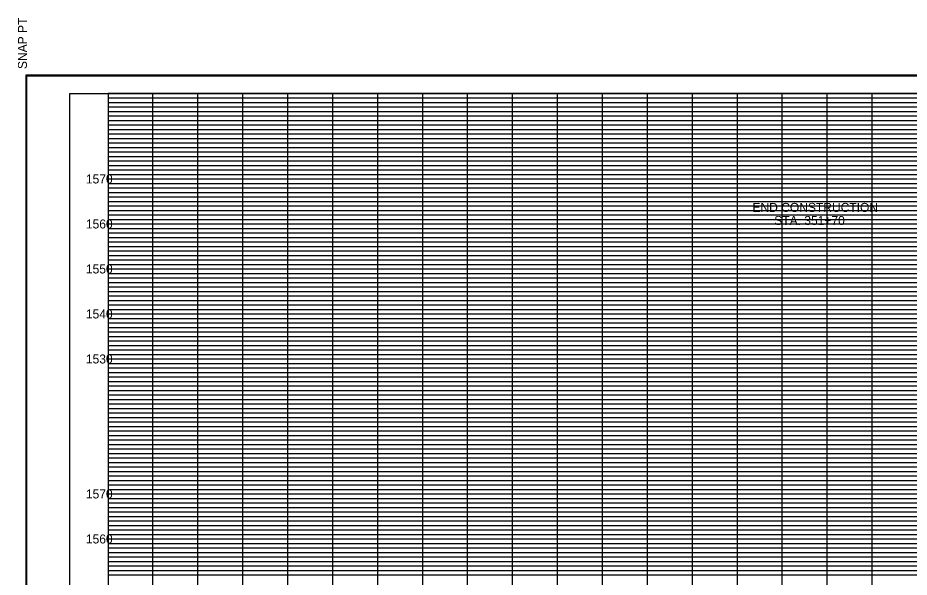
# Model space of a CAD drawing. Extents: x 980 to 1375, y 978 to 1227.
# Drawn here: x 979.9 to 1178.2, y 1102.5 to 1226.8 of the extents above; entities that cross this region are included whole.
import ezdxf

# ---------------------------------------------------------------- set-up
doc = ezdxf.new("R2010")
doc.units = 0
for name, color, linetype in [('DESIGN - SHEET - Corner Text', 7, 'Continuous'), ('DESIGN - SHEET - Light Grid', 7, 'Continuous'), ('DESIGN - SHEET - Linework', 7, 'Continuous'), ('DESIGN - SHEET - Plot Shape', 7, 'Continuous'), ('DESIGN - TYPICAL - Text', 7, 'Continuous')]:
    doc.layers.add(name, color=color, linetype=linetype)

msp = doc.modelspace()

# ---------------------------------------------------------------- linework, layer by layer
at = {"layer": 'DESIGN - SHEET - Light Grid'}
for p, q in [((1000, 1209), (1080, 1209)), ((1000, 1208), (1080, 1208)), ((1080, 1209), (1160, 1209)), ((1080, 1208), (1160, 1208)), ((1160, 1209), (1240, 1209)), ((1160, 1208), (1240, 1208)), ((1000, 1207), (1080, 1207)), ((1000, 1206), (1080, 1206)), ((1080, 1207), (1160, 1207)), ((1080, 1206), (1160, 1206)), ((1160, 1207), (1240, 1207)), ((1160, 1206), (1240, 1206)), ((1000, 1205), (1080, 1205)), ((1000, 1204), (1080, 1204)), ((1080, 1205), (1160, 1205)), ((1080, 1204), (1160, 1204)), ((1160, 1205), (1240, 1205)), ((1160, 1204), (1240, 1204)), ((1000, 1203), (1080, 1203)), ((1000, 1202), (1080, 1202)), ((1080, 1203), (1160, 1203)), ((1080, 1202), (1160, 1202)), ((1160, 1203), (1240, 1203)), ((1160, 1202), (1240, 1202)), ((1000, 1201), (1080, 1201)), ((1080, 1201), (1160, 1201)), ((1160, 1201), (1240, 1201)), ((1000, 1199), (1080, 1199)), ((1000, 1198), (1080, 1198)), ((1080, 1199), (1160, 1199)), ((1080, 1198), (1160, 1198)), ((1160, 1199), (1240, 1199)), ((1160, 1198), (1240, 1198)), ((1000, 1197), (1080, 1197)), ((1000, 1196), (1080, 1196)), ((1080, 1197), (1160, 1197)), ((1080, 1196), (1160, 1196)), ((1160, 1197), (1240, 1197)), ((1160, 1196), (1240, 1196)), ((1000, 1195), (1080, 1195)), ((1000, 1194), (1080, 1194)), ((1080, 1195), (1160, 1195)), ((1080, 1194), (1160, 1194)), ((1160, 1195), (1240, 1195)), ((1160, 1194), (1240, 1194)), ((1000, 1193), (1080, 1193)), ((1000, 1192), (1080, 1192)), ((1080, 1193), (1160, 1193)), ((1080, 1192), (1160, 1192)), ((1160, 1193), (1240, 1193)), ((1160, 1192), (1240, 1192)), ((1000, 1191), (1080, 1191)), ((1080, 1191), (1160, 1191)), ((1160, 1191), (1240, 1191)), ((1000, 1189), (1080, 1189)), ((1000, 1188), (1080, 1188)), ((1080, 1189), (1160, 1189)), ((1080, 1188), (1160, 1188)), ((1160, 1189), (1240, 1189)), ((1160, 1188), (1240, 1188)), ((1000, 1187), (1080, 1187)), ((1000, 1186), (1080, 1186)), ((1080, 1187), (1160, 1187)), ((1080, 1186), (1160, 1186)), ((1160, 1187), (1240, 1187)), ((1160, 1186), (1240, 1186)), ((1000, 1185), (1080, 1185)), ((1000, 1184), (1080, 1184)), ((1080, 1185), (1160, 1185)), ((1080, 1184), (1160, 1184)), ((1160, 1185), (1240, 1185)), ((1160, 1184), (1240, 1184)), ((1000, 1183), (1080, 1183)), ((1000, 1182), (1080, 1182)), ((1080, 1183), (1160, 1183)), ((1080, 1182), (1160, 1182)), ((1160, 1183), (1240, 1183)), ((1160, 1182), (1240, 1182)), ((1000, 1181), (1080, 1181)), ((1080, 1181), (1160, 1181)), ((1160, 1181), (1240, 1181)), ((1000, 1179), (1080, 1179)), ((1000, 1178), (1080, 1178)), ((1080, 1179), (1160, 1179)), ((1080, 1178), (1160, 1178)), ((1160, 1179), (1240, 1179)), ((1160, 1178), (1240, 1178)), ((1000, 1177), (1080, 1177)), ((1000, 1176), (1080, 1176)), ((1080, 1177), (1160, 1177)), ((1080, 1176), (1160, 1176)), ((1160, 1177), (1240, 1177)), ((1160, 1176), (1240, 1176)), ((1000, 1175), (1080, 1175)), ((1000, 1174), (1080, 1174)), ((1080, 1175), (1160, 1175)), ((1080, 1174), (1160, 1174)), ((1160, 1175), (1240, 1175)), ((1160, 1174), (1240, 1174)), ((1000, 1173), (1080, 1173)), ((1000, 1172), (1080, 1172)), ((1080, 1173), (1160, 1173)), ((1080, 1172), (1160, 1172)), ((1160, 1173), (1240, 1173)), ((1160, 1172), (1240, 1172)), ((1000, 1171), (1080, 1171)), ((1080, 1171), (1160, 1171)), ((1160, 1171), (1240, 1171)), ((1000, 1169), (1080, 1169)), ((1000, 1168), (1080, 1168)), ((1080, 1169), (1160, 1169)), ((1080, 1168), (1160, 1168)), ((1160, 1169), (1240, 1169)), ((1160, 1168), (1240, 1168)), ((1000, 1167), (1080, 1167)), ((1000, 1166), (1080, 1166)), ((1080, 1167), (1160, 1167)), ((1080, 1166), (1160, 1166)), ((1160, 1167), (1240, 1167)), ((1160, 1166), (1240, 1166)), ((1000, 1165), (1080, 1165)), ((1000, 1164), (1080, 1164)), ((1080, 1165), (1160, 1165)), ((1080, 1164), (1160, 1164)), ((1160, 1165), (1240, 1165)), ((1160, 1164), (1240, 1164)), ((1000, 1163), (1080, 1163)), ((1000, 1162), (1080, 1162)), ((1080, 1163), (1160, 1163)), ((1080, 1162), (1160, 1162)), ((1160, 1163), (1240, 1163)), ((1160, 1162), (1240, 1162)), ((1000, 1161), (1080, 1161)), ((1080, 1161), (1160, 1161)), ((1160, 1161), (1240, 1161)), ((1000, 1159), (1080, 1159)), ((1000, 1158), (1080, 1158)), ((1080, 1159), (1160, 1159)), ((1080, 1158), (1160, 1158)), ((1160, 1159), (1240, 1159)), ((1160, 1158), (1240, 1158)), ((1000, 1157), (1080, 1157)), ((1000, 1156), (1080, 1156)), ((1080, 1157), (1160, 1157)), ((1080, 1156), (1160, 1156)), ((1160, 1157), (1240, 1157)), ((1160, 1156), (1240, 1156)), ((1000, 1155), (1080, 1155)), ((1000, 1154), (1080, 1154)), ((1080, 1155), (1160, 1155)), ((1080, 1154), (1160, 1154)), ((1160, 1155), (1240, 1155)), ((1160, 1154), (1240, 1154)), ((1000, 1153), (1080, 1153)), ((1000, 1152), (1080, 1152)), ((1080, 1153), (1160, 1153)), ((1080, 1152), (1160, 1152)), ((1160, 1153), (1240, 1153)), ((1160, 1152), (1240, 1152)), ((1000, 1151), (1080, 1151)), ((1080, 1151), (1160, 1151)), ((1160, 1151), (1240, 1151)), ((1000, 1149), (1080, 1149)), ((1080, 1149), (1160, 1149)), ((1160, 1149), (1240, 1149)), ((1000, 1148), (1080, 1148)), ((1000, 1147), (1080, 1147)), ((1080, 1148), (1160, 1148)), ((1080, 1147), (1160, 1147)), ((1160, 1148), (1240, 1148)), ((1160, 1147), (1240, 1147)), ((1000, 1146), (1080, 1146)), ((1000, 1145), (1080, 1145)), ((1080, 1146), (1160, 1146)), ((1080, 1145), (1160, 1145)), ((1160, 1146), (1240, 1146)), ((1160, 1145), (1240, 1145)), ((1000, 1144), (1080, 1144)), ((1000, 1143), (1080, 1143)), ((1080, 1144), (1160, 1144)), ((1080, 1143), (1160, 1143)), ((1160, 1144), (1240, 1144)), ((1160, 1143), (1240, 1143)), ((1000, 1142), (1080, 1142)), ((1000, 1141), (1080, 1141)), ((1080, 1142), (1160, 1142)), ((1080, 1141), (1160, 1141)), ((1160, 1142), (1240, 1142)), ((1160, 1141), (1240, 1141)), ((1000, 1139), (1080, 1139)), ((1080, 1139), (1160, 1139)), ((1160, 1139), (1240, 1139)), ((1000, 1138), (1080, 1138)), ((1000, 1137), (1080, 1137)), ((1080, 1138), (1160, 1138)), ((1080, 1137), (1160, 1137)), ((1160, 1138), (1240, 1138)), ((1160, 1137), (1240, 1137)), ((1000, 1136), (1080, 1136)), ((1000, 1135), (1080, 1135)), ((1080, 1136), (1160, 1136)), ((1080, 1135), (1160, 1135)), ((1160, 1136), (1240, 1136)), ((1160, 1135), (1240, 1135)), ((1000, 1134), (1080, 1134)), ((1000, 1133), (1080, 1133)), ((1080, 1134), (1160, 1134)), ((1080, 1133), (1160, 1133)), ((1160, 1134), (1240, 1134)), ((1160, 1133), (1240, 1133)), ((1000, 1132), (1080, 1132)), ((1000, 1131), (1080, 1131)), ((1080, 1132), (1160, 1132)), ((1080, 1131), (1160, 1131)), ((1160, 1132), (1240, 1132)), ((1160, 1131), (1240, 1131)), ((1000, 1129), (1080, 1129)), ((1080, 1129), (1160, 1129)), ((1160, 1129), (1240, 1129)), ((1000, 1128), (1080, 1128)), ((1000, 1127), (1080, 1127)), ((1080, 1128), (1160, 1128)), ((1080, 1127), (1160, 1127)), ((1160, 1128), (1240, 1128)), ((1160, 1127), (1240, 1127)), ((1000, 1126), (1080, 1126)), ((1000, 1125), (1080, 1125)), ((1080, 1126), (1160, 1126)), ((1080, 1125), (1160, 1125)), ((1160, 1126), (1240, 1126)), ((1160, 1125), (1240, 1125)), ((1000, 1124), (1080, 1124)), ((1000, 1123), (1080, 1123)), ((1080, 1124), (1160, 1124)), ((1080, 1123), (1160, 1123)), ((1160, 1124), (1240, 1124)), ((1160, 1123), (1240, 1123)), ((1000, 1122), (1080, 1122)), ((1000, 1121), (1080, 1121)), ((1080, 1122), (1160, 1122)), ((1080, 1121), (1160, 1121)), ((1160, 1122), (1240, 1122)), ((1160, 1121), (1240, 1121)), ((1000, 1119), (1080, 1119)), ((1080, 1119), (1160, 1119)), ((1160, 1119), (1240, 1119)), ((1000, 1118), (1080, 1118)), ((1000, 1117), (1080, 1117)), ((1080, 1118), (1160, 1118)), ((1080, 1117), (1160, 1117)), ((1160, 1118), (1240, 1118)), ((1160, 1117), (1240, 1117)), ((1000, 1116), (1080, 1116)), ((1000, 1115), (1080, 1115)), ((1080, 1116), (1160, 1116)), ((1080, 1115), (1160, 1115)), ((1160, 1116), (1240, 1116)), ((1160, 1115), (1240, 1115)), ((1000, 1114), (1080, 1114)), ((1000, 1113), (1080, 1113)), ((1080, 1114), (1160, 1114)), ((1080, 1113), (1160, 1113)), ((1160, 1114), (1240, 1114)), ((1160, 1113), (1240, 1113)), ((1000, 1112), (1080, 1112)), ((1000, 1111), (1080, 1111)), ((1080, 1112), (1160, 1112)), ((1080, 1111), (1160, 1111)), ((1160, 1112), (1240, 1112)), ((1160, 1111), (1240, 1111)), ((1000, 1109), (1080, 1109)), ((1080, 1109), (1160, 1109)), ((1160, 1109), (1240, 1109)), ((1000, 1108), (1080, 1108)), ((1000, 1107), (1080, 1107)), ((1080, 1108), (1160, 1108)), ((1080, 1107), (1160, 1107)), ((1160, 1108), (1240, 1108)), ((1160, 1107), (1240, 1107)), ((1000, 1106), (1080, 1106)), ((1000, 1105), (1080, 1105)), ((1080, 1106), (1160, 1106)), ((1080, 1105), (1160, 1105)), ((1160, 1106), (1240, 1106)), ((1160, 1105), (1240, 1105)), ((1000, 1104), (1080, 1104)), ((1000, 1103), (1080, 1103)), ((1080, 1104), (1160, 1104)), ((1080, 1103), (1160, 1103)), ((1160, 1104), (1240, 1104)), ((1160, 1103), (1240, 1103))]:
    msp.add_line(p, q, dxfattribs=at)
at = {"layer": 'DESIGN - SHEET - Linework'}
for p, q in [((981.77, 995.86), (981.77, 1214.14)), ((981.77, 1214.14), (1322.17, 1214.14)), ((1010, 1000), (1010, 1210)), ((1020, 1000), (1020, 1210)), ((1030, 1000), (1030, 1210)), ((1040, 1000), (1040, 1210)), ((1050, 1000), (1050, 1210)), ((1060, 1000), (1060, 1210)), ((1070, 1000), (1070, 1210)), ((1080, 1000), (1080, 1210)), ((1090, 1000), (1090, 1210)), ((1100, 1000), (1100, 1210)), ((1110, 1000), (1110, 1210)), ((1120, 1000), (1120, 1210)), ((1130, 1000), (1130, 1210)), ((1140, 1000), (1140, 1210)), ((1150, 1000), (1150, 1210)), ((1160, 1000), (1160, 1210)), ((1170, 1000), (1170, 1210)), ((1000, 1200), (1280, 1200)), ((1000, 1190), (1320, 1190)), ((1000, 1180), (1320, 1180)), ((1000, 1170), (1320, 1170)), ((1000, 1160), (1320, 1160)), ((1000, 1150), (1320, 1150)), ((1000, 1140), (1320, 1140)), ((1000, 1130), (1320, 1130)), ((1000, 1120), (1320, 1120)), ((1000, 1110), (1320, 1110))]:
    msp.add_line(p, q, dxfattribs=at)
msp.add_lwpolyline([(1000, 1210), (1000, 1000), (1320, 1000), (1320, 1210), (1000, 1210)], dxfattribs=at)
at = {"layer": 'DESIGN - SHEET - Plot Shape'}
for points in [[(981.97, 1213.94), (1321.97, 1213.94), (1321.97, 996.06), (981.97, 996.06)], [(991.5, 1210), (1320, 1210), (1320, 997.5), (991.5, 997.5)]]:
    msp.add_lwpolyline(points, close=True, dxfattribs=at)

# ---------------------------------------------------------------- texts
at = {"layer": 'DESIGN - SHEET - Corner Text'}
msp.add_text('  SNAP PT', height=2, rotation=90, dxfattribs=at).set_placement((981.97, 1213.94))
at = {"layer": 'DESIGN - TYPICAL - Text'}
for s, p in [('     1570     ', (991.37, 1190)), ('END CONSTRUCTION', (1143.36, 1183.68)), ('     1560     ', (991.37, 1180)), ('STA. 351+70', (1148.21, 1180.78)), ('     1550     ', (991.37, 1170)), ('     1540     ', (991.37, 1160)), ('     1530     ', (991.37, 1150)), ('     1570     ', (991.37, 1120)), ('     1560     ', (991.37, 1110))]:
    msp.add_text(s, height=2, dxfattribs=at).set_placement(p)

doc.saveas('drawing.dxf')
